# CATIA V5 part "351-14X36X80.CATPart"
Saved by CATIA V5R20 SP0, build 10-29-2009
Part number: 351-14X36X80
Definition: NONE
Nomenclature: 351-14X36X80
Source: Unknown
Description: 351-14X36X80
Bounding box of the stored display mesh (mm): x -5 to 75, y -12 to 12, z -12 to 12
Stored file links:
  C:\Users\Utente\Desktop\IO LAVORO\3D X SITO CF\X SITO\PLASTICA\351\351-14X36X80.CATPart
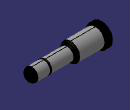
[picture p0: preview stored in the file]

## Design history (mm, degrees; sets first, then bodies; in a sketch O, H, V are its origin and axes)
Body1 "351-14X36X80" (main body)
  Solid1: solid without history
